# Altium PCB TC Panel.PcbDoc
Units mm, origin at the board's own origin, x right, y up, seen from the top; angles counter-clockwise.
Board outline 214.4 x 110 mm, 2 copper layers (Top Layer, Bottom Layer), stack 1.554 mm thick; 6 components, 0 nets, 10 pads, 0 vias.
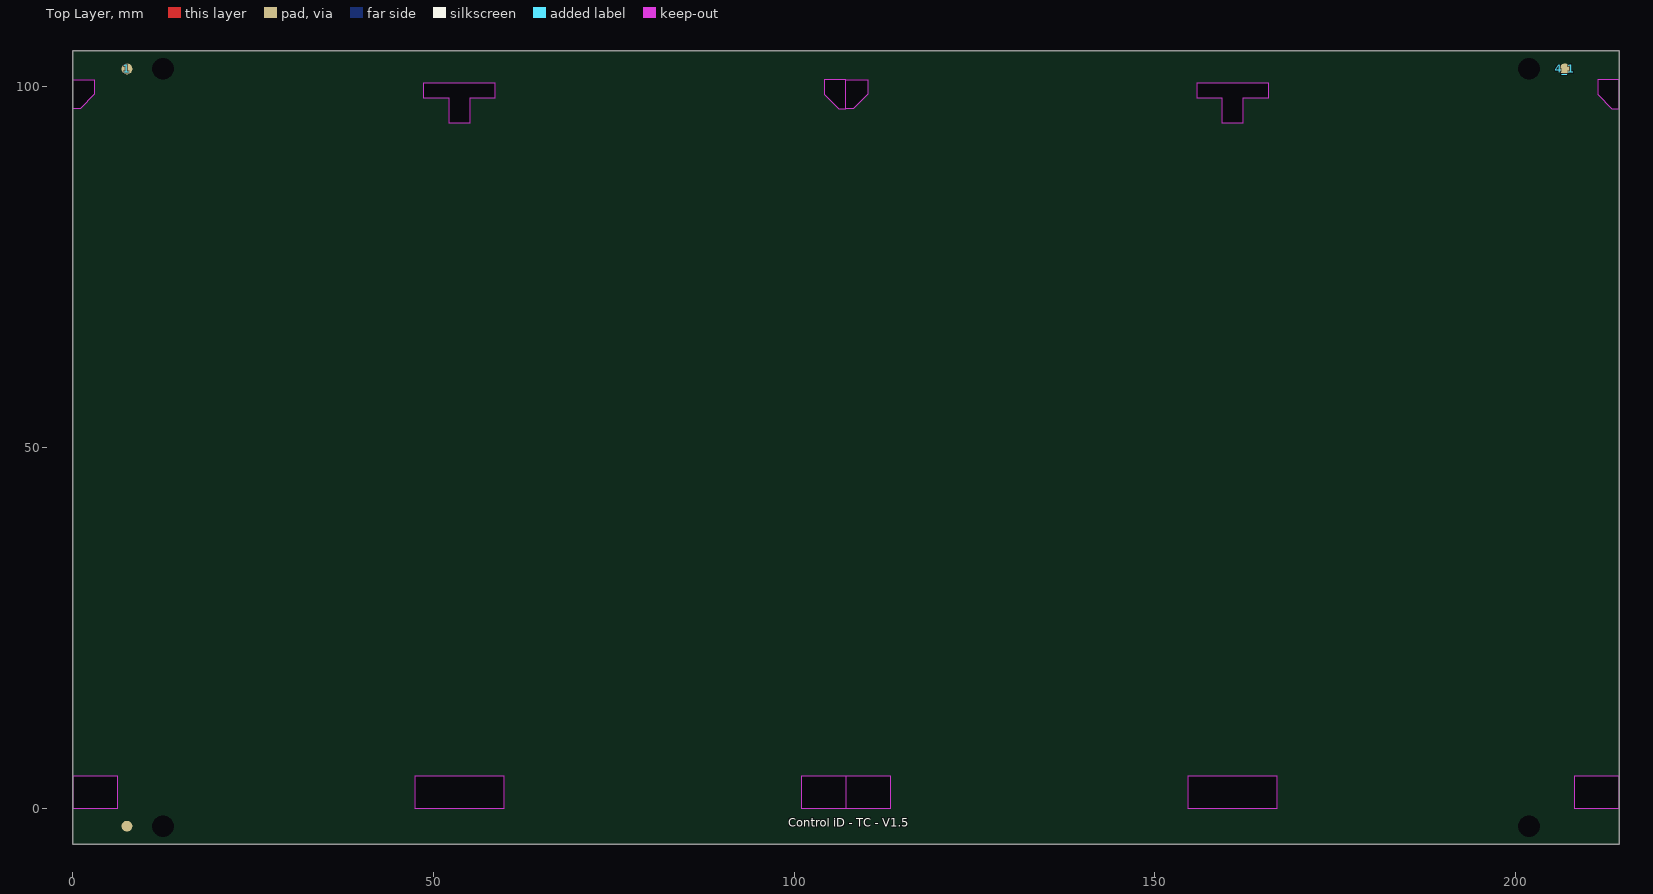
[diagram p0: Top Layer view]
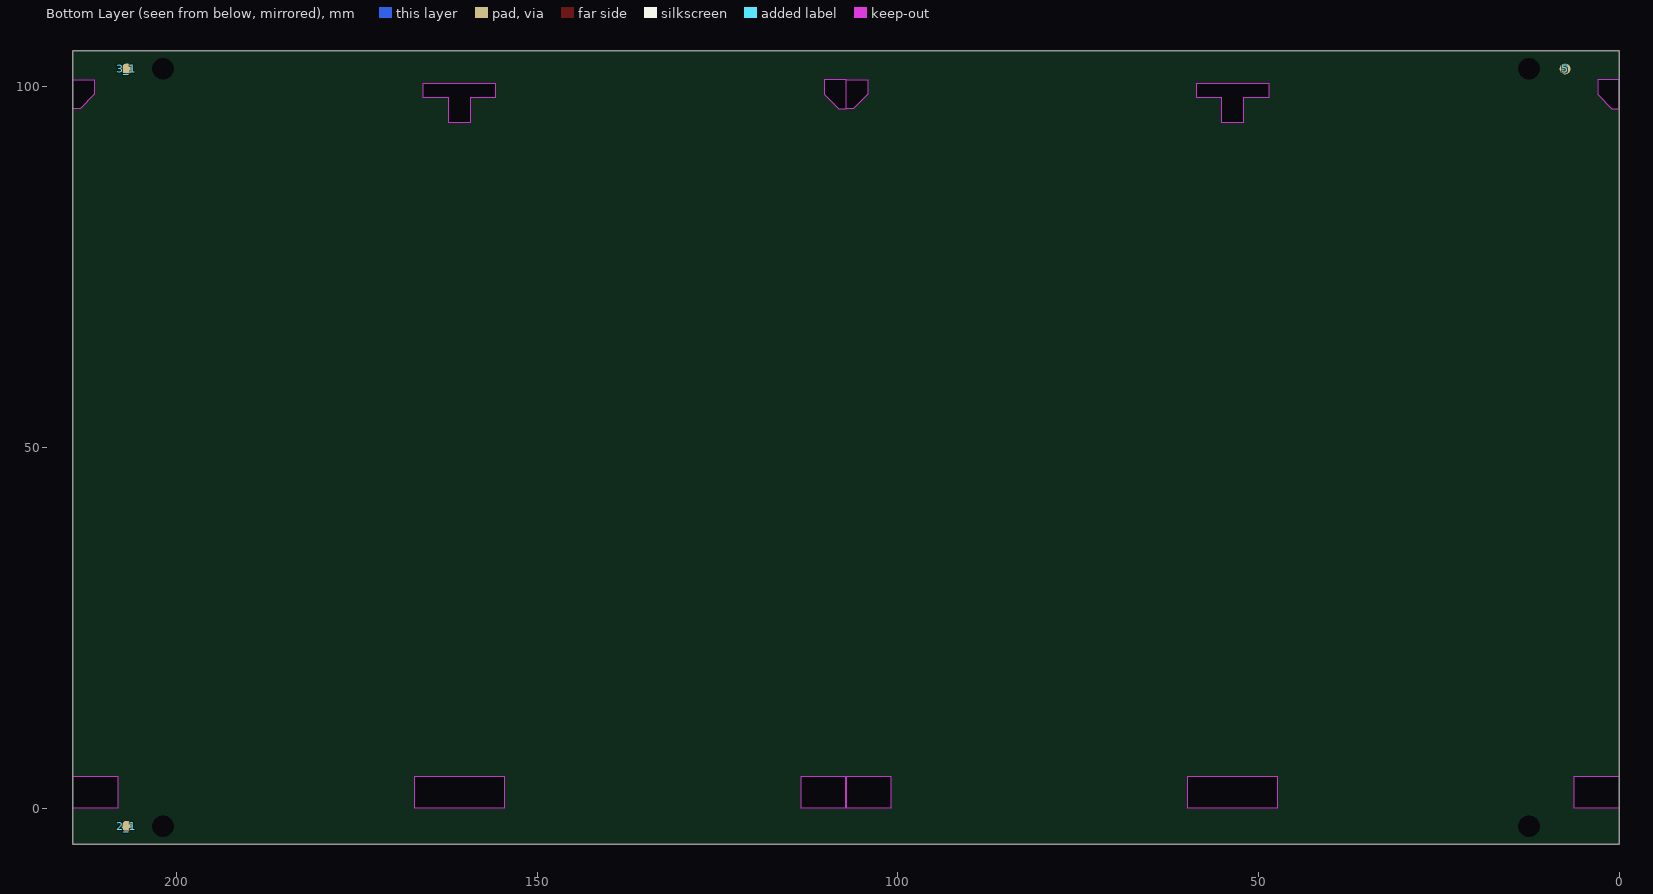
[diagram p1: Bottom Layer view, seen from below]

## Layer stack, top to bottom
Top Solder: solder mask 0.0102, Solder Resist, Dk 3.5
Top Layer: signal copper 0.0356
Dielectric 1: dielectric 1.4834, FR-4, Dk 4.8
Bottom Layer: signal copper 0.0356
Bottom Solder: solder mask 0.0102, Solder Resist, Dk 3.5

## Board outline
0,0 0,105 214.4,105 214.4,-5 0,-5
cut-out: 214.4,97 214.4,101 211.4,101 211.4,99 213.4,97
cut-out: 107.2,97 107.2,101 104.2,101 104.2,99 106.2,97
cut-out: 107.2,97 107.2,101 110.2,101 110.2,99 108.2,97
cut-out: 0,97 0,101 3,101 3,99 1,97
cut-out: 154.6,0 167,0 167,4.4 154.6,4.4
cut-out: 208.2,0 214.4,0 214.4,4.4 208.2,4.4
cut-out: 107.2,0 113.4,0 113.4,4.4 107.2,4.4
cut-out: 159.3,98.5 159.3,95 162.3,95 162.3,98.5 165.8,98.5 165.8,100.5 155.8,100.5 155.8,98.5
cut-out: 52.1,98.5 52.1,95 55.1,95 55.1,98.5 58.6,98.5 58.6,100.5 48.6,100.5 48.6,98.5
cut-out: 0,0 6.2,0 6.2,4.4 0,4.4
cut-out: 101,0 107.2,0 107.2,4.4 101,4.4
cut-out: 47.4,0 59.8,0 59.8,4.4 47.4,4.4

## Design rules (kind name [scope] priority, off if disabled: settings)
Clearance [All] p1: gap=0.254 ignorepadtopadclearanceinfootprint=FALSE except(0: Arc-Hole Track-Hole SMDPad-Hole THPad-Hole Via-Hole Fill-Hole Poly-Hole Region-Hole Text-Hole)
PolygonConnect [All] p1: connectstyle=Relief reliefconductorwidth=0.254 reliefentries=4 polygonreliefangle="90 Angle" airgapwidth=0.254
RoutingVias [All] p1: holewidth=0.711 width=1.27 viastyle="Through Hole" minholewidth=0.711 minwidth=1.27 maxholewidth=0.711 maxwidth=1.27
SolderMaskExpansion [All] p1: expansion=0.102
Width [All] p1: maxlimit=0.254 minlimit=0.254 preferedwidth=0.254
30 further rules are at their usual default settings.

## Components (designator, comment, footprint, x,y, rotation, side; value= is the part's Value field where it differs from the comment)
1 "" FIDUCIAL-1.5X3 7.5,102.5 r180 top
2_1 "" FIDUCIAL-1.5X3 206.9,-2.5 r0 bottom
3_1 "" FIDUCIAL-1.5X3 206.9,102.5 r180 bottom
4_1 "" FIDUCIAL-1.5X3 206.9,102.5 r0 top
5 "" FIDUCIAL-1.5X3 7.5,102.5 r180 bottom
? "" FIDUCIAL-1.5X3 7.5,-2.5 r0 top

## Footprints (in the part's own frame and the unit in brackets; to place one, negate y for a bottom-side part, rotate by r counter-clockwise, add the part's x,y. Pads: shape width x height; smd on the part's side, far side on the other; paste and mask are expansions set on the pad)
FIDUCIAL-1.5X3 [mm]
  rrect100% 1.5x1.5 smd: 1(0,0)

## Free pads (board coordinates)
  round 0 hole 3 unplated: 0(12.5,-2.5) 0(12.5,102.5) 0(201.9,-2.5) 0(201.9,102.5)

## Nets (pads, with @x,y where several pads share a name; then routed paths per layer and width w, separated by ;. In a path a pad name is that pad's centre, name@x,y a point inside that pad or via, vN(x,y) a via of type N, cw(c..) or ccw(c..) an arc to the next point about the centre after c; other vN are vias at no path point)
pads on no net: 1.1 2_1.1 3_1.1 4_1.1 5.1 ?.1

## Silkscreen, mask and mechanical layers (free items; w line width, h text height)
Top Overlay:
  text "Control iD - TC - V1.5" at 99.2,-3 h2
Mechanical 1:
  drawing of 194 lines, arcs and shapes, not listed

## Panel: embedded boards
"TC.PcbDoc" at 160.8,100, 1 rows x 1 columns, spacing 63.5 x 38.1, rotation 180
"TC.PcbDoc" at 160.8,100, 1 rows x 1 columns, spacing 63.5 x 38.1, rotation 180
"TC.PcbDoc" at 53.6,100, 1 rows x 1 columns, spacing 63.5 x 38.1, rotation 180
"TC.PcbDoc" at 53.6,100, 1 rows x 1 columns, spacing 63.5 x 38.1, rotation 180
